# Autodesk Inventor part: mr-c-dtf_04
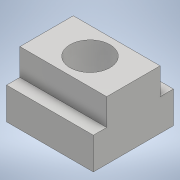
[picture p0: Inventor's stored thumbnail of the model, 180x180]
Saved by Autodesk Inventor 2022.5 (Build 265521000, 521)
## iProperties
Part Number: mr-c-dtf_04
Material: 一般
Document SubType Name: Modeling
Designer: ImaoCorp
Density: 1 g/cm^3
Appearance: 既定
Author: ImaoCorp
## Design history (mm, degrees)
feature "mr-c-dtf_04"
node "ソリッド1"
